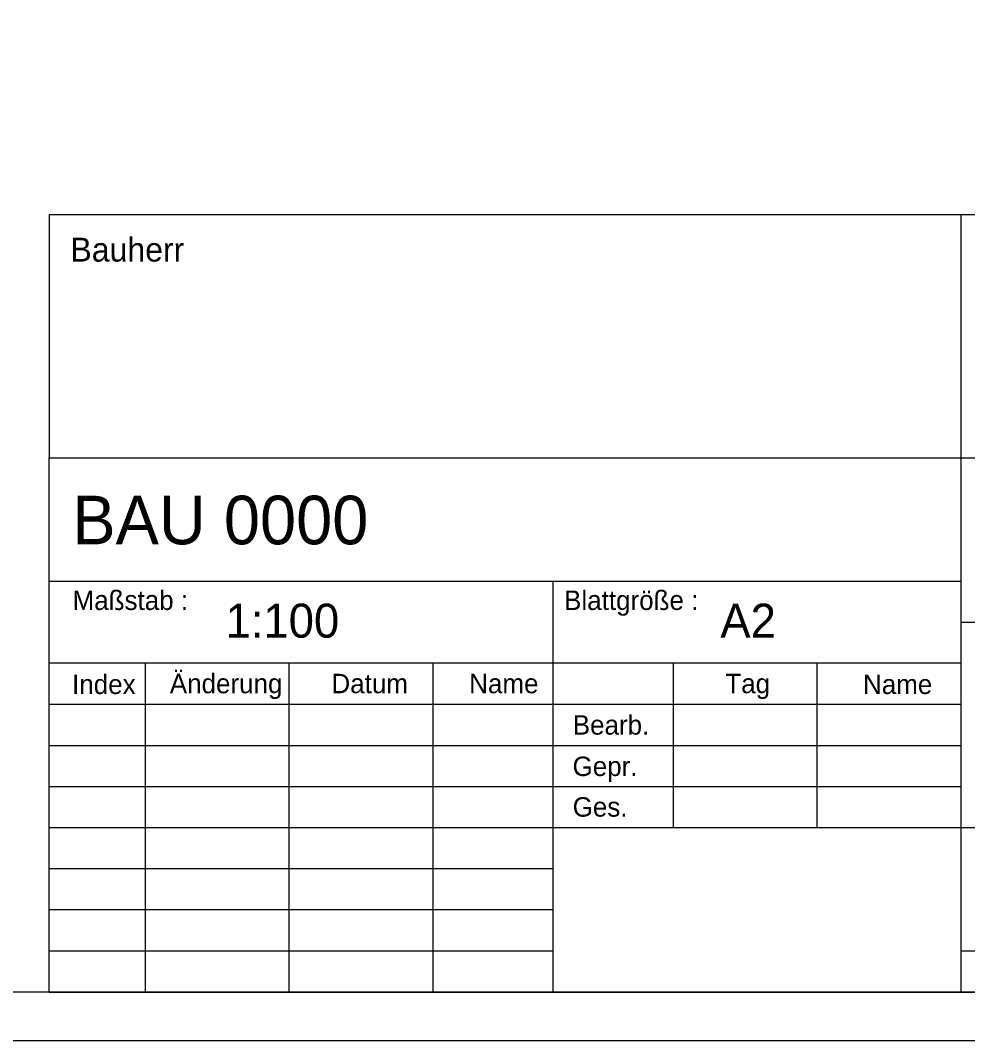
# Model space of a CAD drawing. Extents: x 0 to 59.4, y 0 to 42.
# Drawn here: x 40.82 to 50.57, y 0 to 10.5 of the extents above; entities that cross this region are included whole.
import ezdxf

# ---------------------------------------------------------------- set-up
doc = ezdxf.new("R2010")
doc.units = 0
doc.layers.add('90_Plankopf', color=7, linetype='Continuous')

msp = doc.modelspace()

# ---------------------------------------------------------------- linework, layer by layer
at = {"layer": '90_Plankopf'}
for p, q in [((58.9, 8.499), (41.112, 8.499)), ((41.112, 8.499), (41.112, 5.999)), ((50.5, 5.999), (50.5, 8.499)), ((41.112, 5.999), (58.9, 5.999)), ((41.112, 0.5), (41.112, 5.999)), ((41.112, 5.999), (58.9, 5.999)), ((50.5, 0.5), (50.5, 5.999)), ((41.112, 4.73), (50.5, 4.73)), ((46.3, 0.5), (46.3, 4.73)), ((50.5, 4.307), (58.9, 4.307)), ((41.112, 3.887), (50.5, 3.887)), ((42.1, 3.884), (42.1, 0.5)), ((43.583, 0.5), (43.583, 3.884)), ((45.065, 0.5), (45.065, 3.884)), ((47.535, 3.884), (47.535, 2.192)), ((49.018, 2.192), (49.018, 3.884)), ((41.112, 3.463), (50.5, 3.463)), ((41.112, 3.038), (50.5, 3.038)), ((41.112, 2.615), (50.5, 2.615)), ((41.112, 2.192), (50.5, 2.192)), ((41.112, 2.192), (50.5, 2.192)), ((46.3, 2.192), (50.5, 2.192)), ((50.5, 2.192), (58.9, 2.192)), ((46.3, 1.769), (41.112, 1.769)), ((46.3, 1.346), (41.112, 1.346)), ((41.112, 0.923), (46.3, 0.923)), ((50.5, 0.923), (58.9, 0.923)), ((58.9, 0.5), (41.112, 0.5)), ((41.112, 0.5), (46.3, 0.5)), ((42.28, 0.5), (58.9, 0.5)), ((42.28, 0.5), (58.9, 0.5))]:
    msp.add_line(p, q, dxfattribs=at)
for points in [[(0, 0), (59.4, 0), (59.4, 42), (0, 42)], [(2.5, 41.5), (58.9, 41.5), (58.9, 0.5), (2.5, 0.5)]]:
    msp.add_lwpolyline(points, close=True, dxfattribs=at)

# ---------------------------------------------------------------- texts
for s, height, p in [('Bauherr', 0.2464, (41.33, 8.018)), ('BAU 0000      ', 0.5, (41.349, 5.108)), ('Maßstab :', 0.2, (41.352, 4.432)), ('Blattgröße :', 0.19999, (46.412, 4.432)), ('1:100    ', 0.35, (42.926, 4.147)), ('A2       ', 0.35, (48.02, 4.147)), ('Änderung', 0.2, (42.353, 3.575)), ('Index', 0.2, (41.347, 3.567)), ('Datum', 0.2, (44.017, 3.575)), ('Name', 0.2, (45.435, 3.575)), ('Tag', 0.2, (48.072, 3.575)), ('Name', 0.2, (49.489, 3.567)), ('Bearb.', 0.2, (46.501, 3.149)), ('Gepr.', 0.2, (46.499, 2.723)), ('Ges.', 0.2, (46.5, 2.305))]:
    msp.add_text(s, height=height, dxfattribs=at).set_placement(p)

doc.saveas('drawing.dxf')
